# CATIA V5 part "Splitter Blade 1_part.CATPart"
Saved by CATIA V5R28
Part number: Splitter Blade 1_part
Definition: design
Nomenclature: Splitter Blade 1_part
Source: Unknown
Bounding box of the stored display mesh (mm): x 0.177 to 4.812, y -10.089 to -1.975, z 4.237 to 7.742
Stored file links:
  D:\paraturbo-cad\STEP\Turbocompressor_for_Christophe\Splitter Blade 1_part.CATPart
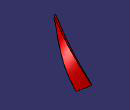
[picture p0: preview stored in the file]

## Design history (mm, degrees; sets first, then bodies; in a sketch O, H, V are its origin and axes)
Body1 "MANIFOLD_SOLID_BREP #60000" (main body)
  Solid1: solid without history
